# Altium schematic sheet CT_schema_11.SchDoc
size 387 x 278 mm
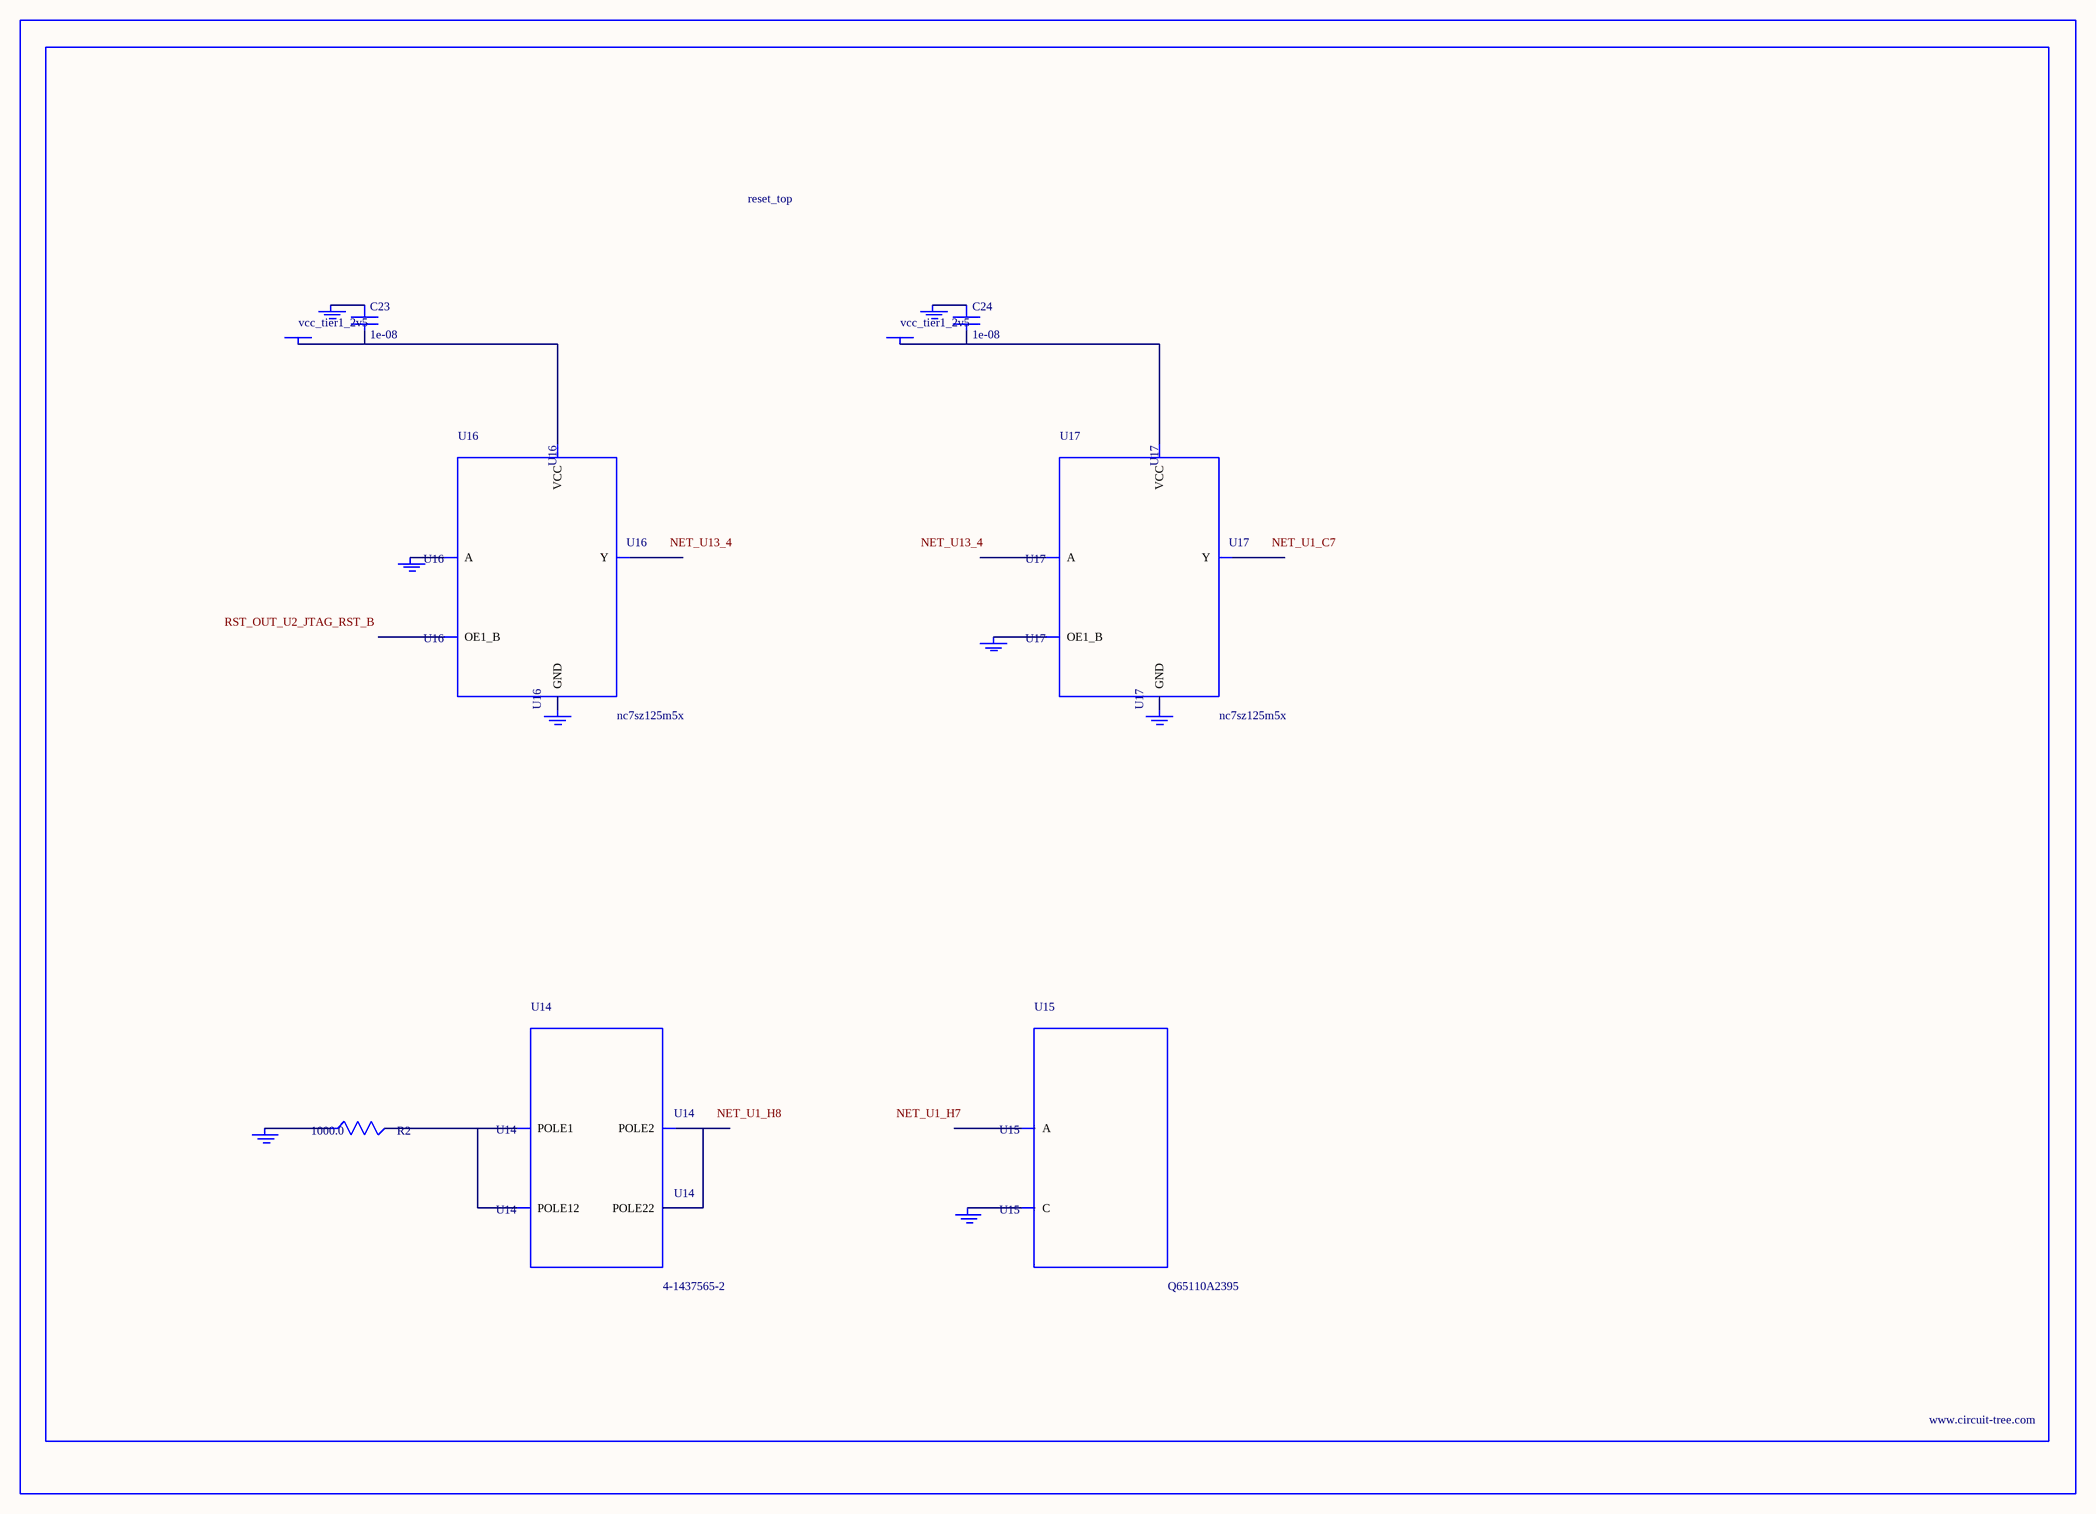
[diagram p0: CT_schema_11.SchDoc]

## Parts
BORDER10  (no value)
C23  1e-08  [C0402]
C24  1e-08  [C0402]
GND_INSTANCE_10_0  (no value)
GND_INSTANCE_10_1  (no value)
GND_INSTANCE_10_2  (no value)
GND_INSTANCE_10_3  (no value)
GND_INSTANCE_10_4  (no value)
GND_INSTANCE_10_5  (no value)
GND_INSTANCE_10_6  (no value)
GND_INSTANCE_10_7  (no value)
POWER_INSTANCE_10_0  vcc_tier1_2v5
POWER_INSTANCE_10_1  vcc_tier1_2v5
R2  1000.0  [R0603]
U14  4-1437565-2  [SW_4-1437565-2]
U15  Q65110A2395  [LGM67K-G1J2-24-Z]
U16  nc7sz125m5x  [NC7SZ125M5X]
U17  nc7sz125m5x  [NC7SZ125M5X]

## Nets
NetC23_1: C23.1 GND_INSTANCE_10_2.0(GND)
NetC23_2: C23.2 POWER_INSTANCE_10_0.0(PWR) U16.5(VCC)
NetC24_1: C24.1 GND_INSTANCE_10_5.0(GND)
NetC24_2: C24.2 POWER_INSTANCE_10_1.0(PWR) U17.5(VCC)
NetGND_INSTANCE_10_0_0: GND_INSTANCE_10_0.0(GND) R2.1
NetGND_INSTANCE_10_1_0: GND_INSTANCE_10_1.0(GND) U15.C
NetGND_INSTANCE_10_3_0: GND_INSTANCE_10_3.0(GND) U16.2(A)
NetGND_INSTANCE_10_4_0: GND_INSTANCE_10_4.0(GND) U16.3(GND)
NetGND_INSTANCE_10_6_0: GND_INSTANCE_10_6.0(GND) U17.1(OE1_B)
NetGND_INSTANCE_10_7_0: GND_INSTANCE_10_7.0(GND) U17.3(GND)
NetR2_2: R2.2 U14.1(POLE1) U14.2(POLE12)
NetU14_3: U14.3(POLE2) U14.4(POLE22)

Not connected (* = marked no-connect by the designer): U15 A; U16 1(OE1_B) 4(Y); U17 2(A) 4(Y)

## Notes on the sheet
- Labels drawn without touching a wire or pin: NET_U1_C7, NET_U1_H7, NET_U1_H8, NET_U13_4, RST_OUT_U2_JTAG_RST_B

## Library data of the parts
BORDER10 = BORDER_PAGE10
C23 C24 = C0402C103K3RAC
GND_INSTANCE_10_0-GND_INSTANCE_10_7 = GND
POWER_INSTANCE_10_0 POWER_INSTANCE_10_1 = PWR
R2 = RC0603JR-071KL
